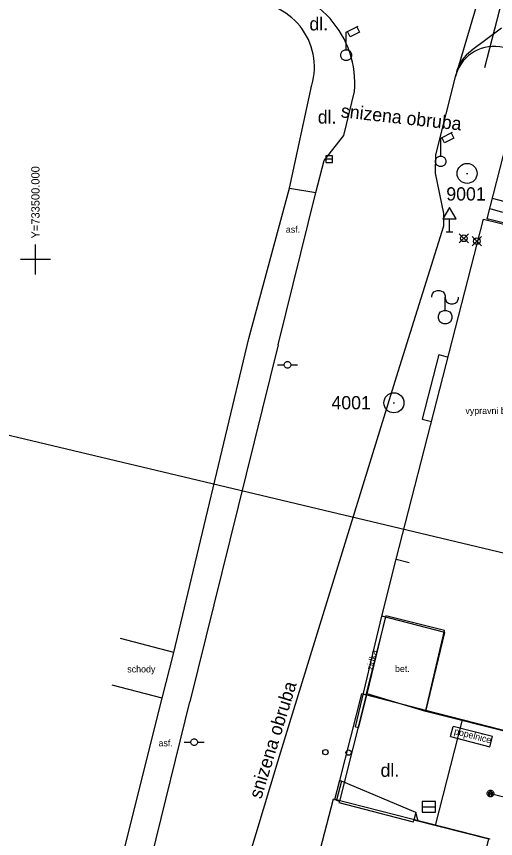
# Model space of a CAD drawing. Extents: x -733601 to -733291, y -1137892 to -1137187.
# Drawn here: x -733501.4 to -733465.3, y -1137693.7 to -1137631.7 of the extents above; entities that cross this region are included whole.
import ezdxf

# ---------------------------------------------------------------- set-up
doc = ezdxf.new("R2010")
doc.units = 0
for name, color, linetype in [('BP_NOVE_NAVRH', 7, 'Continuous'), ('BP_PBPP_pouzito_pro_map_podklady', 7, 'Continuous'), ('Default', 7, 'Continuous'), ('Krizky_Hektom_sit', 7, 'Continuous'), ('Rozvrzeni', 7, 'Continuous'), ('SIT_PROJ', 7, 'Continuous'), ('SIT_PUV_BUS', 7, 'Continuous'), ('SIT_PUV_ZELEZNICE', 7, 'Continuous')]:
    doc.layers.add(name, color=color, linetype=linetype)

# ---------------------------------------------------------------- blocks, each defined once
blk = doc.blocks.new('POINT_DISPLAY')
at = {"layer": 'Default'}
for p, q in [((-0.7, -0.7), (0.7, 0.7)), ((-0.7, 0.7), (0.7, -0.7))]:
    blk.add_line(p, q, dxfattribs=at)
blk.add_circle((0, 0), 0.5, dxfattribs=at)
blk = doc.blocks.new('vytyc_bod_MP')
at = {"layer": 'Default'}
blk.add_blockref('POINT_DISPLAY', (0, 0), dxfattribs=at)

msp = doc.modelspace()

# ---------------------------------------------------------------- linework, layer by layer
at = {"layer": 'BP_NOVE_NAVRH'}
msp.add_line((-733472.979, -1137660.826), (-733472.879, -1137660.826), dxfattribs=at)
msp.add_circle((-733472.929, -1137660.826), 0.756, dxfattribs=at)
at = {"layer": 'BP_PBPP_pouzito_pro_map_podklady'}
msp.add_line((-733467.456, -1137643.512), (-733467.356, -1137643.512), dxfattribs=at)
msp.add_circle((-733467.406, -1137643.512), 0.756, dxfattribs=at)
at = {"layer": 'Krizky_Hektom_sit'}
for p, q in [((-733500, -1137651.131), (-733500, -1137648.869)), ((-733498.869, -1137650), (-733501.131, -1137650))]:
    msp.add_line(p, q, dxfattribs=at)
at = {"layer": 'Rozvrzeni'}
msp.add_lwpolyline([(-733564.934, -1137648.317), (-733492.008, -1137341.875), (-733347.542, -1137376.254), (-733420.468, -1137682.696)], close=True, dxfattribs=at)
at = {"layer": 'SIT_PROJ'}
for points in [[(-733463.07, -1137623.85), (-733466.099, -1137635.551)], [(-733468.24, -1137636.02), (-733468.285, -1137636.201)]]:
    msp.add_lwpolyline(points, dxfattribs=at)
msp.add_arc((-733465.38, -1137636.926), 3, 75.9059, 162.41584, dxfattribs=at)
at = {"layer": 'SIT_PUV_BUS'}
for p, q in [((-733460.86, -1137611.32), (-733468.24, -1137636.02)), ((-733476.54, -1137632.84), (-733475.64, -1137632.39)), ((-733476.54, -1137634.19), (-733476.54, -1137632.84)), ((-733476.24, -1137633.19), (-733476.44, -1137632.79)), ((-733475.54, -1137632.84), (-733476.24, -1137633.19)), ((-733475.74, -1137632.44), (-733475.54, -1137632.84)), ((-733464.8, -1137632.55), (-733467.06, -1137634.23)), ((-733476.94, -1137634.49), (-733476.84, -1137634.29)), ((-733476.94, -1137634.69), (-733476.94, -1137634.49)), ((-733476.84, -1137634.89), (-733476.94, -1137634.69)), ((-733476.84, -1137634.29), (-733476.64, -1137634.19)), ((-733476.64, -1137634.19), (-733476.44, -1137634.19)), ((-733476.44, -1137634.19), (-733476.24, -1137634.29)), ((-733476.24, -1137634.29), (-733476.14, -1137634.49)), ((-733476.14, -1137634.69), (-733476.24, -1137634.89)), ((-733476.14, -1137634.49), (-733476.14, -1137634.69)), ((-733476.64, -1137634.99), (-733476.84, -1137634.89)), ((-733476.44, -1137634.99), (-733476.64, -1137634.99)), ((-733476.24, -1137634.89), (-733476.44, -1137634.99)), ((-733469.76, -1137642.11), (-733468.24, -1137636.02)), ((-733480.82, -1137644.62), (-733479.13, -1137636.83)), ((-733476.7, -1137640.64), (-733475.91, -1137637.33)), ((-733478.2, -1137642.54), (-733476.7, -1137640.64)), ((-733469.4, -1137640.85), (-733468.5, -1137640.4)), ((-733469.4, -1137642.2), (-733469.4, -1137640.85)), ((-733469.1, -1137641.2), (-733469.3, -1137640.8)), ((-733468.4, -1137640.85), (-733469.1, -1137641.2)), ((-733468.6, -1137640.45), (-733468.4, -1137640.85)), ((-733469.8, -1137643.5), (-733469.76, -1137642.11)), ((-733478.83, -1137644.96), (-733478.2, -1137642.54)), ((-733477.56, -1137642.19), (-733478.06, -1137642.19)), ((-733478.06, -1137642.19), (-733478.06, -1137642.69)), ((-733477.56, -1137642.44), (-733478.06, -1137642.44)), ((-733478.06, -1137642.69), (-733477.56, -1137642.69)), ((-733477.56, -1137642.69), (-733477.56, -1137642.19)), ((-733469.8, -1137642.5), (-733469.7, -1137642.3)), ((-733469.8, -1137642.7), (-733469.8, -1137642.5)), ((-733469.7, -1137642.9), (-733469.8, -1137642.7)), ((-733469.7, -1137642.3), (-733469.5, -1137642.2)), ((-733469.5, -1137642.2), (-733469.3, -1137642.2)), ((-733469.3, -1137642.2), (-733469.1, -1137642.3)), ((-733469.1, -1137642.3), (-733469, -1137642.5)), ((-733469, -1137642.7), (-733469.1, -1137642.9)), ((-733469, -1137642.5), (-733469, -1137642.7)), ((-733469.5, -1137643), (-733469.7, -1137642.9)), ((-733469.3, -1137643), (-733469.5, -1137643)), ((-733469.1, -1137642.9), (-733469.3, -1137643)), ((-733469.16, -1137646.53), (-733469.8, -1137643.5)), ((-733483.88, -1137655.97), (-733480.82, -1137644.62)), ((-733480.82, -1137644.62), (-733478.83, -1137644.96)), ((-733481.66, -1137656.44), (-733478.83, -1137644.96)), ((-733468.73, -1137646.08), (-733469.23, -1137646.93)), ((-733469.16, -1137647.48), (-733469.16, -1137646.53)), ((-733468.23, -1137646.93), (-733468.73, -1137646.08)), ((-733472.76, -1137672.63), (-733466.17, -1137646.96)), ((-733469.23, -1137646.93), (-733468.23, -1137646.93)), ((-733468.73, -1137647.93), (-733468.73, -1137646.93)), ((-733466.17, -1137646.96), (-733456.56, -1137649.32)), ((-733472.74, -1137658.87), (-733469.16, -1137647.48)), ((-733468.98, -1137647.93), (-733468.48, -1137647.93)), ((-733470.06, -1137652.76), (-733470.01, -1137652.61)), ((-733470.01, -1137652.61), (-733469.91, -1137652.46)), ((-733469.91, -1137652.46), (-733469.66, -1137652.36)), ((-733469.66, -1137652.36), (-733469.46, -1137652.36)), ((-733469.46, -1137652.36), (-733469.21, -1137652.46)), ((-733469.21, -1137652.46), (-733469.11, -1137652.61)), ((-733469.11, -1137652.61), (-733469.06, -1137652.76)), ((-733470.06, -1137652.86), (-733470.06, -1137652.76)), ((-733469.06, -1137652.76), (-733469.06, -1137652.96)), ((-733469.06, -1137653.86), (-733469.06, -1137652.86)), ((-733469.06, -1137652.96), (-733468.96, -1137653.21)), ((-733468.96, -1137653.21), (-733468.81, -1137653.31)), ((-733468.81, -1137653.31), (-733468.66, -1137653.36)), ((-733468.66, -1137653.36), (-733468.46, -1137653.36)), ((-733468.46, -1137653.36), (-733468.31, -1137653.31)), ((-733468.31, -1137653.31), (-733468.16, -1137653.21)), ((-733468.16, -1137653.21), (-733468.06, -1137652.96)), ((-733468.06, -1137652.96), (-733468.06, -1137652.86)), ((-733469.51, -1137654.11), (-733469.41, -1137653.96)), ((-733469.41, -1137653.96), (-733469.16, -1137653.86)), ((-733469.16, -1137653.86), (-733468.96, -1137653.86)), ((-733468.96, -1137653.86), (-733468.71, -1137653.96)), ((-733468.71, -1137653.96), (-733468.61, -1137654.11)), ((-733469.56, -1137654.26), (-733469.51, -1137654.11)), ((-733469.56, -1137654.46), (-733469.56, -1137654.26)), ((-733469.46, -1137654.71), (-733469.56, -1137654.46)), ((-733468.56, -1137654.46), (-733468.66, -1137654.71)), ((-733468.61, -1137654.11), (-733468.56, -1137654.26)), ((-733468.56, -1137654.26), (-733468.56, -1137654.46)), ((-733469.31, -1137654.81), (-733469.46, -1137654.71)), ((-733469.16, -1137654.86), (-733469.31, -1137654.81)), ((-733468.96, -1137654.86), (-733469.16, -1137654.86)), ((-733468.81, -1137654.81), (-733468.96, -1137654.86)), ((-733468.66, -1137654.71), (-733468.81, -1137654.81)), ((-733489.54, -1137679.68), (-733483.88, -1137655.97)), ((-733481.66, -1137656.44), (-733488.33, -1137683.41)), ((-733481.11, -1137657.75), (-733481.01, -1137657.7)), ((-733481.01, -1137657.7), (-733480.91, -1137657.7)), ((-733480.91, -1137657.7), (-733480.81, -1137657.75)), ((-733469.54, -1137657.19), (-733470.79, -1137662.07)), ((-733469.54, -1137657.19), (-733468.84, -1137657.37)), ((-733481.71, -1137657.95), (-733481.21, -1137657.95)), ((-733481.21, -1137657.9), (-733481.16, -1137657.8)), ((-733481.21, -1137658), (-733481.21, -1137657.9)), ((-733481.16, -1137658.1), (-733481.21, -1137658)), ((-733481.16, -1137657.8), (-733481.11, -1137657.75)), ((-733481.11, -1137658.15), (-733481.16, -1137658.1)), ((-733481.01, -1137658.2), (-733481.11, -1137658.15)), ((-733480.91, -1137658.2), (-733481.01, -1137658.2)), ((-733480.81, -1137658.15), (-733480.91, -1137658.2)), ((-733480.81, -1137657.75), (-733480.76, -1137657.8)), ((-733480.76, -1137658.1), (-733480.81, -1137658.15)), ((-733480.76, -1137657.8), (-733480.71, -1137657.9)), ((-733480.71, -1137658), (-733480.76, -1137658.1)), ((-733480.71, -1137657.9), (-733480.71, -1137658)), ((-733480.71, -1137657.95), (-733480.21, -1137657.95)), ((-733480.68, -1137684.62), (-733472.74, -1137658.87)), ((-733470.79, -1137662.07), (-733470.09, -1137662.25)), ((-733473.84, -1137676.94), (-733472.76, -1137672.63)), ((-733472.76, -1137672.63), (-733471.79, -1137672.88)), ((-733475.84, -1137685.29), (-733473.84, -1137676.94)), ((-733469.08, -1137678.16), (-733473.84, -1137676.94)), ((-733474.96, -1137682.8), (-733473.56, -1137677.05)), ((-733470.52, -1137684.13), (-733469.08, -1137678.16)), ((-733489.54, -1137679.68), (-733493.57, -1137678.62)), ((-733490.44, -1137683.13), (-733489.54, -1137679.68)), ((-733490.44, -1137683.13), (-733494.21, -1137682.14)), ((-733497.16, -1137709.97), (-733490.44, -1137683.13)), ((-733475.58, -1137685.32), (-733474.96, -1137682.8)), ((-733470.52, -1137684.13), (-733474.96, -1137682.8)), ((-733495.01, -1137710.47), (-733488.33, -1137683.41)), ((-733462.88, -1137686.05), (-733470.52, -1137684.13)), ((-733481.67, -1137687.82), (-733480.68, -1137684.62)), ((-733475.84, -1137685.29), (-733475.58, -1137685.32)), ((-733468.65, -1137686.02), (-733468.45, -1137685.25)), ((-733465.49, -1137686.01), (-733468.45, -1137685.25)), ((-733488.21, -1137686.29), (-733488.16, -1137686.24)), ((-733488.16, -1137686.24), (-733488.06, -1137686.19)), ((-733488.06, -1137686.19), (-733487.96, -1137686.19)), ((-733487.96, -1137686.19), (-733487.86, -1137686.24)), ((-733487.86, -1137686.24), (-733487.81, -1137686.29)), ((-733468.65, -1137686.02), (-733465.69, -1137686.79)), ((-733465.69, -1137686.79), (-733465.49, -1137686.01)), ((-733488.76, -1137686.44), (-733488.26, -1137686.44)), ((-733488.26, -1137686.39), (-733488.21, -1137686.29)), ((-733488.26, -1137686.49), (-733488.26, -1137686.39)), ((-733488.21, -1137686.59), (-733488.26, -1137686.49)), ((-733488.16, -1137686.64), (-733488.21, -1137686.59)), ((-733488.06, -1137686.69), (-733488.16, -1137686.64)), ((-733487.96, -1137686.69), (-733488.06, -1137686.69)), ((-733487.86, -1137686.64), (-733487.96, -1137686.69)), ((-733487.81, -1137686.59), (-733487.86, -1137686.64)), ((-733487.81, -1137686.29), (-733487.76, -1137686.39)), ((-733487.76, -1137686.49), (-733487.81, -1137686.59)), ((-733487.76, -1137686.39), (-733487.76, -1137686.49)), ((-733487.76, -1137686.44), (-733487.26, -1137686.44)), ((-733484.97, -1137698.72), (-733481.67, -1137687.82)), ((-733465.88, -1137690.27), (-733465.83, -1137690.17)), ((-733465.88, -1137690.37), (-733465.88, -1137690.27)), ((-733465.83, -1137690.47), (-733465.88, -1137690.37)), ((-733465.83, -1137690.17), (-733465.78, -1137690.12)), ((-733465.78, -1137690.52), (-733465.83, -1137690.47)), ((-733465.78, -1137690.12), (-733465.68, -1137690.07)), ((-733465.78, -1137690.22), (-733465.78, -1137690.42)), ((-733465.78, -1137690.42), (-733465.68, -1137690.47)), ((-733465.68, -1137690.57), (-733465.78, -1137690.52)), ((-733465.68, -1137690.07), (-733465.58, -1137690.07)), ((-733465.68, -1137690.47), (-733465.68, -1137690.17)), ((-733465.68, -1137690.17), (-733465.58, -1137690.17)), ((-733465.58, -1137690.57), (-733465.68, -1137690.57)), ((-733465.63, -1137690.32), (-733451.03, -1137693.87)), ((-733465.58, -1137690.07), (-733465.48, -1137690.12)), ((-733465.58, -1137690.17), (-733465.58, -1137690.47)), ((-733465.58, -1137690.47), (-733465.48, -1137690.42)), ((-733465.48, -1137690.52), (-733465.58, -1137690.57)), ((-733465.48, -1137690.12), (-733465.43, -1137690.17)), ((-733465.48, -1137690.42), (-733465.48, -1137690.22)), ((-733465.43, -1137690.47), (-733465.48, -1137690.52)), ((-733465.43, -1137690.17), (-733465.38, -1137690.27)), ((-733465.38, -1137690.37), (-733465.43, -1137690.47)), ((-733465.38, -1137690.27), (-733465.38, -1137690.37)), ((-733482.78, -1137711.2), (-733477.5, -1137690.71)), ((-733477.5, -1137690.71), (-733465.66, -1137693.73)), ((-733469.79, -1137690.93), (-733470.79, -1137690.93)), ((-733470.79, -1137690.93), (-733470.79, -1137691.73)), ((-733469.79, -1137691.73), (-733469.79, -1137690.93)), ((-733470.79, -1137691.33), (-733469.79, -1137691.33)), ((-733470.79, -1137691.73), (-733469.79, -1137691.73))]:
    msp.add_line(p, q, dxfattribs=at)
for centre in [(-733478.1, -1137687.2), (-733476.35, -1137687.23)]:
    msp.add_circle(centre, 0.2, dxfattribs=at)
for centre, radius, start, end in [((-733483.25, -1137636.73), 7.367, 355.26097, 88.28476), ((-733483.82, -1137635.47), 4.886, 343.74472, 93.9812), ((-733465.4, -1137636.61), 2.899, 124.72939, 168.18662)]:
    msp.add_arc(centre, radius, start, end, dxfattribs=at)
at = {"layer": 'SIT_PUV_ZELEZNICE'}
for p, q in [((-733465.899, -1137646.951), (-733464.426, -1137641.243)), ((-733464.53, -1137645.65), (-733465.497, -1137645.392)), ((-733465.773, -1137646.983), (-733465.899, -1137646.951)), ((-733475.39, -1137682.788), (-733477.042, -1137689.34)), ((-733477.02, -1137690.889), (-733475.002, -1137682.885)), ((-733475.002, -1137682.885), (-733475.39, -1137682.788)), ((-733470.522, -1137684.041), (-733475.039, -1137682.876)), ((-733477.042, -1137689.34), (-733477.408, -1137690.791)), ((-733476.896, -1137689.377), (-733477.042, -1137689.34)), ((-733476.896, -1137689.377), (-733477.262, -1137690.829)), ((-733471.286, -1137691.751), (-733476.896, -1137689.377)), ((-733471.286, -1137691.751), (-733471.431, -1137692.323)), ((-733471.1, -1137692.408), (-733471.286, -1137691.751))]:
    msp.add_line(p, q, dxfattribs=at)
for points in [[(-733465.696, -1137646.166), (-733464.73, -1137646.425)], [(-733462.935, -1137685.963), (-733461.332, -1137679.64), (-733453.759, -1137650.014), (-733456.593, -1137649.288), (-733465.899, -1137646.951)], [(-733462.935, -1137685.963), (-733463.955, -1137685.738), (-733470.522, -1137684.041), (-733469.12, -1137678.024), (-733473.546, -1137676.915), (-733475.039, -1137682.876), (-733475.39, -1137682.788)], [(-733467.778, -1137684.75), (-733469.812, -1137692.738)], [(-733477.042, -1137689.34), (-733476.896, -1137689.377), (-733477.262, -1137690.829), (-733477.02, -1137690.889)], [(-733477.05, -1137690.883), (-733477.408, -1137690.791)], [(-733477.05, -1137690.883), (-733477.082, -1137691.009), (-733471.464, -1137692.449), (-733471.431, -1137692.323)], [(-733470.978, -1137714.118), (-733465.765, -1137693.775), (-733471.431, -1137692.323)]]:
    msp.add_lwpolyline(points, dxfattribs=at)

# ---------------------------------------------------------------- block references
at = {"layer": 'SIT_PROJ', "xscale": 0.5, "yscale": 0.5}
for p in [(-733467.648, -1137648.409), (-733466.674, -1137648.632)]:
    msp.add_blockref('vytyc_bod_MP', p, dxfattribs=at)

# ---------------------------------------------------------------- texts
at = {"layer": 'BP_NOVE_NAVRH'}
msp.add_text('4001', height=1, dxfattribs=at).set_placement((-733477.646, -1137661.318))
at = {"layer": 'BP_PBPP_pouzito_pro_map_podklady'}
msp.add_text('9001', height=1, dxfattribs=at).set_placement((-733468.975, -1137645.557))
at = {"layer": 'Krizky_Hektom_sit'}
msp.add_text('Y=733500.000', height=0.625, rotation=90, dxfattribs=at).set_placement((-733499.685, -1137648.425))
at = {"layer": 'SIT_PUV_BUS'}
for s, height, p in [('dl.', 1, (-733479.31, -1137632.72)), ('dl.', 1, (-733478.68, -1137639.75)), ('asf.', 0.5, (-733481.09, -1137647.99)), ('vypravni budova', 0.5, (-733467.53, -1137661.67)), ('schody', 0.5, (-733493.06, -1137681.18)), ('bet.', 0.5, (-733472.85, -1137681.15)), ('asf.', 0.5, (-733490.7, -1137686.76)), ('dl.', 1, (-733473.94, -1137689.06))]:
    msp.add_text(s, height=height, dxfattribs=at).set_placement(p)
for s, height, rotation, p in [('snizena obruba', 1, 353.7, (-733476.97, -1137639.27)), ('zidka', 0.5, 75.6, (-733474.53, -1137681.06)), ('snizena obruba', 1, 72.9, (-733482.95, -1137690.78)), ('popelnice', 0.5, 345.6, (-733468.42, -1137685.83))]:
    msp.add_text(s, height=height, rotation=rotation, dxfattribs=at).set_placement(p)

doc.saveas('drawing.dxf')
